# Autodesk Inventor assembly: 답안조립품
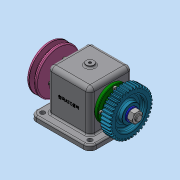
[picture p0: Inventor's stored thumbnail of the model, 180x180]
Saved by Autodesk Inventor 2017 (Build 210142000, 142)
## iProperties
Part Number: 답안조립품
Material: 일반
Document SubType Name: Assembly
Designer: MRC
Author: MRC
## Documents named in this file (12)
- C:\Users\MRC\Desktop\720706V1017\답안조립품.iam
- C:\Users\MRC\Desktop\720706V1017\V벨트풀리.ipt
- C:\Users\MRC\Desktop\720706V1017\너트 M12x1.25.ipt
- C:\Users\MRC\Desktop\720706V1017\베어링 6204.ipt
- C:\Users\MRC\Desktop\720706V1017\본체.ipt
- C:\Users\MRC\Desktop\720706V1017\볼트 M4x0.7.ipt
- C:\Users\MRC\Desktop\720706V1017\스퍼기어.ipt
- C:\Users\MRC\Desktop\720706V1017\오일실 20x35x8.ipt
- C:\Users\MRC\Desktop\720706V1017\와셔 12x24.ipt
- C:\Users\MRC\Desktop\720706V1017\축.ipt
- C:\Users\MRC\Desktop\720706V1017\커버.ipt
- C:\Users\MRC\Desktop\720706V1017\키 5x5.ipt
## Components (1 placed, 1 different names)
1. V벨트풀리:1
